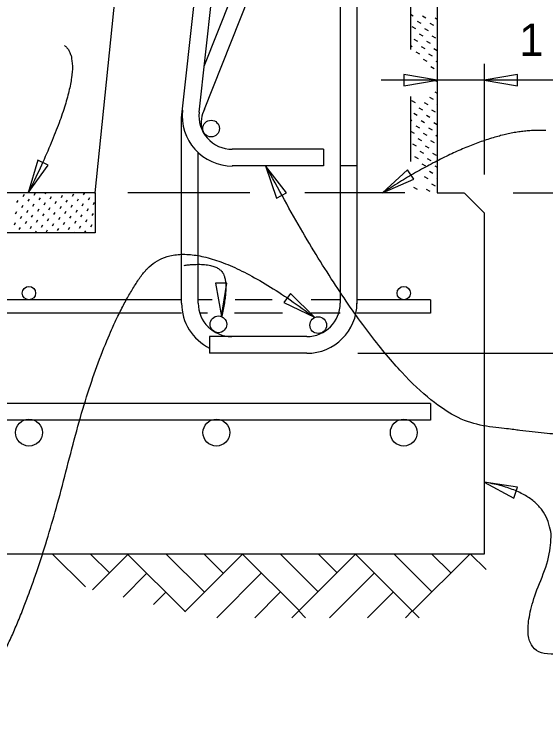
# Model space of a CAD drawing. Extents: x 120632.7 to 120668.8, y 120715.7 to 120740.6.
# Drawn here: x 120647.369 to 120649.025, y 120721.94 to 120724.135 of the extents above; entities that cross this region are included whole.
import ezdxf

# ---------------------------------------------------------------- set-up
doc = ezdxf.new("R2010")
doc.units = 0
for name, color, linetype in [('Dimension', 7, 'Continuous'), ('Miscellaneous', 7, 'Continuous'), ('Rebar', 7, 'Continuous'), ('Rebar_h', 7, 'Continuous'), ('TextStructures', 7, 'Continuous'), ('TrafBarrierConc', 7, 'Continuous')]:
    doc.layers.add(name, color=color, linetype=linetype)

msp = doc.modelspace()

# ---------------------------------------------------------------- linework, layer by layer
at = {"layer": 'Dimension'}
for p, q in [((120648.8323, 120723.9797), (120648.8323, 120723.6349)), ((120649.179, 120723.9287), (120648.512, 120723.9287)), ((120648.9227, 120723.5784), (120649.8324, 120723.5784)), ((120648.4393, 120723.0784), (120649.8324, 120723.0784))]:
    msp.add_line(p, q, dxfattribs=at)
for points in [[(120648.6865, 120723.9287), (120648.5824, 120723.9463), (120648.5824, 120723.9111)], [(120648.8323, 120723.9287), (120648.9364, 120723.9111), (120648.9364, 120723.9463)], [(120647.4136, 120723.5784), (120647.4754, 120723.6641), (120647.4437, 120723.6797)], [(120648.1525, 120723.6618), (120648.1861, 120723.5617), (120648.2172, 120723.5783)], [(120648.5166, 120723.5784), (120648.6135, 120723.6203), (120648.5943, 120723.6499)], [(120648.0155, 120723.1927), (120648.0312, 120723.2971), (120647.9959, 120723.2964)], [(120648.304, 120723.1905), (120648.2293, 120723.2651), (120648.2089, 120723.2364)], [(120648.8323, 120722.6775), (120648.9255, 120722.6278), (120648.9366, 120722.6612)]]:
    msp.add_lwpolyline(points, close=True, dxfattribs=at)
for points in [[(120647.5267, 120724.0367), (120647.6082, 120723.9741), (120647.4137, 120723.5784)], [(120649.0248, 120723.7719), (120648.8351, 120723.7851), (120648.5167, 120723.5784)], [(120649.2188, 120722.8171), (120649.0928, 120722.8171), (120648.5664, 120722.8891), (120648.1526, 120723.6618)], [(120646.75, 120721.9408), (120647.2284, 120721.9277), (120647.4429, 120722.3562), (120647.6394, 120723.1429), (120647.8936, 120723.5), (120648.3041, 120723.1905)], [(120647.8985, 120723.3524), (120647.9863, 120723.3637), (120648.0421, 120723.3067), (120648.0155, 120723.1926)], [(120649.2457, 120722.1418), (120649.167, 120722.1418), (120648.9128, 120722.1418), (120649.1153, 120722.6303), (120648.8323, 120722.6775)]]:
    msp.add_open_spline(points, degree=2, dxfattribs=at)
at = {"layer": 'Miscellaneous'}
for p, q in [((120648.6032, 120724.8007), (120648.6032, 120724.0249)), ((120648.6032, 120724.1346), (120648.612, 120724.1295)), ((120648.6238, 120724.113), (120648.635, 120724.1065)), ((120648.6403, 120724.1295), (120648.6515, 120724.123)), ((120648.6798, 120724.123), (120648.6865, 120724.1191)), ((120648.6073, 120724.0965), (120648.6185, 120724.09)), ((120648.6468, 120724.09), (120648.658, 120724.0835)), ((120648.6633, 120724.1065), (120648.6745, 120724.1)), ((120648.6303, 120724.0735), (120648.6415, 120724.067)), ((120648.6863, 120724.0835), (120648.6865, 120724.0834)), ((120648.6138, 120724.057), (120648.625, 120724.0505)), ((120648.6533, 120724.0505), (120648.6645, 120724.044)), ((120648.6698, 120724.067), (120648.681, 120724.0605)), ((120648.6032, 120724.0371), (120648.6085, 120724.034)), ((120648.6368, 120724.034), (120648.648, 120724.0275)), ((120648.6762, 120724.0275), (120648.6865, 120724.0216)), ((120648.6203, 120724.0175), (120648.6315, 120724.011)), ((120648.6597, 120724.011), (120648.6709, 120724.0046)), ((120648.6432, 120723.9945), (120648.6544, 120723.9881)), ((120648.6827, 120723.9881), (120648.6865, 120723.9859)), ((120648.6662, 120723.9716), (120648.6774, 120723.9651)), ((120648.6727, 120723.9321), (120648.6839, 120723.9256)), ((120648.6792, 120723.8926), (120648.6865, 120723.8884)), ((120648.6032, 120723.8786), (120648.6032, 120723.6758)), ((120648.6627, 120723.8761), (120648.6739, 120723.8696)), ((120648.6067, 120723.8661), (120648.6179, 120723.8596)), ((120648.6462, 120723.8596), (120648.6574, 120723.8531)), ((120648.6857, 120723.8531), (120648.6865, 120723.8526)), ((120648.6132, 120723.8266), (120648.6244, 120723.8201)), ((120648.6297, 120723.8431), (120648.6409, 120723.8366)), ((120648.6692, 120723.8366), (120648.6804, 120723.8301)), ((120648.6032, 120723.8063), (120648.6079, 120723.8036)), ((120648.6527, 120723.8201), (120648.6639, 120723.8136)), ((120648.6197, 120723.7871), (120648.6309, 120723.7806)), ((120648.6362, 120723.8036), (120648.6474, 120723.7971)), ((120648.6757, 120723.7971), (120648.6865, 120723.7908)), ((120648.6032, 120723.7706), (120648.6144, 120723.7641)), ((120648.6427, 120723.7641), (120648.6539, 120723.7577)), ((120648.6592, 120723.7806), (120648.6704, 120723.7742)), ((120648.6262, 120723.7476), (120648.6374, 120723.7412)), ((120648.6656, 120723.7412), (120648.6768, 120723.7347)), ((120648.6821, 120723.7577), (120648.6865, 120723.7551)), ((120648.6097, 120723.7311), (120648.6209, 120723.7247)), ((120648.6491, 120723.7247), (120648.6603, 120723.7182)), ((120648.6032, 120723.7088), (120648.6044, 120723.7082)), ((120648.6326, 120723.7082), (120648.6438, 120723.7017)), ((120648.6721, 120723.7017), (120648.6833, 120723.6952)), ((120648.6161, 120723.6917), (120648.6273, 120723.6852)), ((120648.6556, 120723.6852), (120648.6668, 120723.6787)), ((120648.6391, 120723.6687), (120648.6503, 120723.6622)), ((120648.6786, 120723.6622), (120648.6865, 120723.6576)), ((120648.6456, 120723.6292), (120648.6568, 120723.6227)), ((120648.6621, 120723.6457), (120648.6733, 120723.6392)), ((120648.6851, 120723.6227), (120648.6865, 120723.6219)), ((120648.6126, 120723.5962), (120648.6238, 120723.5897)), ((120648.6521, 120723.5897), (120648.6633, 120723.5832)), ((120648.6686, 120723.6062), (120648.6798, 120723.5997)), ((120647.6222, 120723.5784), (120645.9812, 120723.5784)), ((120647.3977, 120723.5671), (120647.4017, 120723.5741)), ((120647.4322, 120723.5712), (120647.4363, 120723.5782)), ((120647.4475, 120723.556), (120647.4515, 120723.5629)), ((120647.4668, 120723.5752), (120647.4686, 120723.5784)), ((120647.482, 120723.56), (120647.4861, 120723.567)), ((120647.5166, 120723.5641), (120647.5206, 120723.5711)), ((120647.5511, 120723.5681), (120647.5552, 120723.5751)), ((120647.5857, 120723.5722), (120647.5893, 120723.5784)), ((120647.6009, 120723.5569), (120647.605, 120723.5639)), ((120647.6202, 120723.5762), (120647.6215, 120723.5784)), ((120647.3784, 120723.5478), (120647.3824, 120723.5548)), ((120647.4129, 120723.5519), (120647.417, 120723.5589)), ((120647.4282, 120723.5367), (120647.4322, 120723.5437)), ((120647.4627, 120723.5407), (120647.4668, 120723.5477)), ((120647.4973, 120723.5448), (120647.5013, 120723.5518)), ((120647.5318, 120723.5488), (120647.5359, 120723.5558)), ((120647.5471, 120723.5336), (120647.5511, 120723.5406)), ((120647.5664, 120723.5529), (120647.5704, 120723.5599)), ((120647.5816, 120723.5376), (120647.5857, 120723.5446)), ((120647.6162, 120723.5417), (120647.6202, 120723.5487)), ((120647.3743, 120723.5133), (120647.3784, 120723.5203)), ((120647.3936, 120723.5326), (120647.3977, 120723.5396)), ((120647.4089, 120723.5174), (120647.4129, 120723.5244)), ((120647.4434, 120723.5214), (120647.4475, 120723.5284)), ((120647.478, 120723.5255), (120647.482, 120723.5325)), ((120647.5125, 120723.5295), (120647.5166, 120723.5365)), ((120647.5278, 120723.5143), (120647.5318, 120723.5213)), ((120647.5623, 120723.5183), (120647.5664, 120723.5253)), ((120647.5969, 120723.5224), (120647.6009, 120723.5294)), ((120647.3896, 120723.4981), (120647.3936, 120723.5051)), ((120647.4241, 120723.5021), (120647.4282, 120723.5091)), ((120647.4587, 120723.5062), (120647.4627, 120723.5132)), ((120647.4739, 120723.4909), (120647.478, 120723.4979)), ((120647.4932, 120723.5102), (120647.4973, 120723.5172)), ((120647.5085, 120723.495), (120647.5125, 120723.502)), ((120647.543, 120723.499), (120647.5471, 120723.506)), ((120647.5776, 120723.5031), (120647.5816, 120723.5101)), ((120647.6121, 120723.5071), (120647.6162, 120723.5141)), ((120647.3703, 120723.4788), (120647.3743, 120723.4858)), ((120647.4048, 120723.4828), (120647.4089, 120723.4898)), ((120647.4201, 120723.4676), (120647.4241, 120723.4746)), ((120647.4394, 120723.4869), (120647.4434, 120723.4939)), ((120647.4546, 120723.4716), (120647.4587, 120723.4786)), ((120647.4892, 120723.4757), (120647.4932, 120723.4827)), ((120647.5237, 120723.4797), (120647.5278, 120723.4867)), ((120647.5583, 120723.4838), (120647.5623, 120723.4908)), ((120647.5735, 120723.4685), (120647.5776, 120723.4755)), ((120647.5928, 120723.4878), (120647.5969, 120723.4948)), ((120647.6081, 120723.4726), (120647.6121, 120723.4796)), ((120647.3855, 120723.4635), (120647.3896, 120723.4705)), ((120647.4038, 120723.4534), (120647.4048, 120723.4553)), ((120647.4359, 120723.4534), (120647.4394, 120723.4593)), ((120647.4699, 120723.4564), (120647.4739, 120723.4634)), ((120647.5044, 120723.4604), (120647.5085, 120723.4674)), ((120647.539, 120723.4645), (120647.543, 120723.4715)), ((120647.5566, 120723.4534), (120647.5583, 120723.4562)), ((120647.5888, 120723.4534), (120647.5928, 120723.4603)), ((120647.5917, 120722.351), (120647.4893, 120722.4534)), ((120647.6661, 120722.3945), (120647.6072, 120722.4534)), ((120647.725, 120722.4534), (120647.6132, 120722.3417)), ((120647.9006, 120722.2755), (120647.7227, 120722.4534)), ((120647.8429, 120722.4534), (120647.9607, 120722.3356)), ((120648.0797, 120722.4523), (120647.9017, 120722.2744)), ((120647.9607, 120722.4534), (120648.0196, 120722.3945)), ((120648.2564, 120722.2779), (120648.0809, 120722.4534)), ((120648.3154, 120722.3368), (120648.1987, 120722.4534)), ((120648.432, 120722.4534), (120648.2564, 120722.2779)), ((120648.3743, 120722.3957), (120648.3166, 120722.4534)), ((120648.6088, 120722.2767), (120648.4321, 120722.4534)), ((120648.5523, 120722.4534), (120648.6689, 120722.3368)), ((120648.7878, 120722.4534), (120648.6099, 120722.2756)), ((120648.6701, 120722.4534), (120648.7278, 120722.3957)), ((120648.8384, 120722.4053), (120648.7903, 120722.4534)), ((120647.7827, 120722.3934), (120647.7085, 120722.3191)), ((120648.1386, 120722.3934), (120648.0004, 120722.2552)), ((120648.491, 120722.3945), (120648.3516, 120722.2552)), ((120647.8417, 120722.3344), (120647.8038, 120722.2966)), ((120648.1975, 120722.3345), (120648.1183, 120722.2552)), ((120648.5499, 120722.3356), (120648.4695, 120722.2552)), ((120647.9006, 120722.2755), (120647.8991, 120722.2741)), ((120647.9029, 120722.2732), (120647.9017, 120722.2744)), ((120648.2553, 120722.2767), (120648.2338, 120722.2552)), ((120648.2553, 120722.2767), (120648.2768, 120722.2552)), ((120648.6088, 120722.2767), (120648.5873, 120722.2552)), ((120648.6303, 120722.2552), (120648.6099, 120722.2756))]:
    msp.add_line(p, q, dxfattribs=at)
at = {"layer": 'Rebar'}
for p, q in [((120647.8906, 120723.8122), (120648.124, 120725.9221)), ((120648.3845, 120725.9221), (120648.3845, 120723.2346)), ((120648.4366, 120725.9221), (120648.4366, 120723.2324)), ((120647.945, 120723.8295), (120648.1117, 120725.3363)), ((120647.9608, 120723.9726), (120648.2807, 120724.7782)), ((120647.9621, 120723.8389), (120648.3231, 120724.748)), ((120647.8906, 120723.2346), (120647.8906, 120723.8122)), ((120647.8906, 120723.2346), (120647.8906, 120723.7784)), ((120647.9427, 120723.2346), (120647.9427, 120723.7031)), ((120648.3323, 120723.7139), (120648.0485, 120723.7139)), ((120648.3323, 120723.7139), (120648.3323, 120723.6618)), ((120648.3323, 120723.6618), (120648.0485, 120723.6618)), ((120648.4366, 120723.6618), (120648.3844, 120723.6618)), ((120648.2803, 120723.1305), (120647.9781, 120723.1305)), ((120647.9781, 120723.1305), (120647.9781, 120723.0784)), ((120648.2803, 120723.0784), (120647.9781, 120723.0784))]:
    msp.add_line(p, q, dxfattribs=at)
for centre in [(120647.9826, 120723.7783), (120648.0053, 120723.1687), (120648.3161, 120723.1663)]:
    msp.add_circle(centre, 0.026, dxfattribs=at)
for centre, radius, start, end in [((120648.0487, 120723.818), 0.1563, 173.6886, 270), ((120648.0487, 120723.818), 0.1042, 173.6886, 270), ((120648.0527, 120723.7932), 0.1013, 153.2679, 188.7672), ((120648.0469, 120723.2346), 0.1562, 180, 243.8961), ((120648.0469, 120723.2346), 0.1042, 180, 270), ((120648.2804, 120723.2346), 0.1562, 270, 0), ((120648.2804, 120723.2346), 0.1042, 270, 0)]:
    msp.add_arc(centre, radius, start, end, dxfattribs=at)
at = {"layer": 'Rebar_h'}
for p, q in [((120647.8906, 120723.2451), (120646.4298, 120723.2451)), ((120647.9855, 120723.2451), (120647.9427, 120723.2451)), ((120648.1725, 120723.2451), (120648.0575, 120723.2451)), ((120648.3845, 120723.2451), (120648.2943, 120723.2451)), ((120648.6656, 120723.2451), (120648.4365, 120723.2451)), ((120648.6656, 120723.2451), (120648.6656, 120723.2034)), ((120647.8906, 120723.2034), (120646.4298, 120723.2034)), ((120647.9715, 120723.2034), (120647.9475, 120723.2034)), ((120648.2049, 120723.2034), (120648.0558, 120723.2034)), ((120648.3845, 120723.2034), (120648.2943, 120723.2034)), ((120648.6656, 120723.2034), (120648.4365, 120723.2034)), ((120648.6656, 120722.9221), (120646.4515, 120722.9221)), ((120648.6656, 120722.9221), (120648.6656, 120722.8701)), ((120648.6656, 120722.8701), (120646.4515, 120722.8701))]:
    msp.add_line(p, q, dxfattribs=at)
for centre, radius in [((120647.4157, 120723.2658), 0.0208), ((120648.5824, 120723.2658), 0.0208), ((120647.4158, 120722.8315), 0.0417), ((120647.9991, 120722.8315), 0.0417), ((120648.5824, 120722.8315), 0.0417)]:
    msp.add_circle(centre, radius, dxfattribs=at)
at = {"layer": 'TrafBarrierConc'}
for p, q in [((120647.6221, 120723.5784), (120647.8885, 120726.1829)), ((120648.6865, 120725.1409), (120648.6865, 120723.5784)), ((120647.6222, 120723.5784), (120647.6222, 120723.4534)), ((120648.103, 120723.5784), (120647.7231, 120723.5784)), ((120648.5856, 120723.5784), (120648.274, 120723.5784)), ((120648.6865, 120723.5784), (120648.7698, 120723.5784)), ((120648.8324, 120723.5159), (120648.7699, 120723.5784)), ((120648.8323, 120723.5159), (120648.8323, 120722.4534)), ((120647.6222, 120723.4534), (120646.3578, 120723.4534)), ((120648.8323, 120722.4534), (120645.9811, 120722.4534))]:
    msp.add_line(p, q, dxfattribs=at)

# ---------------------------------------------------------------- texts
at = {"layer": 'TextStructures'}
msp.add_text('1', height=0.1008, dxfattribs=at).set_placement((120648.9421, 120724.0045))

doc.saveas('drawing.dxf')
